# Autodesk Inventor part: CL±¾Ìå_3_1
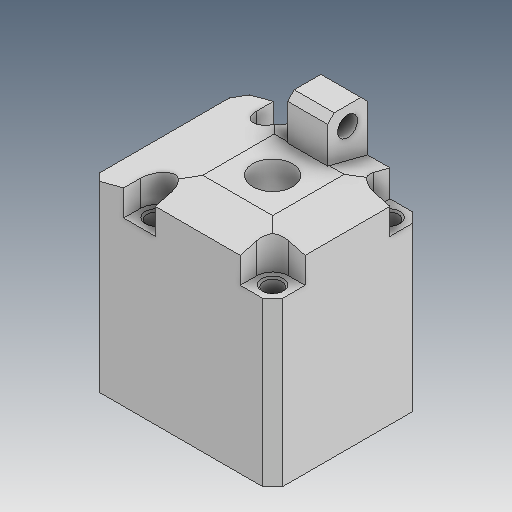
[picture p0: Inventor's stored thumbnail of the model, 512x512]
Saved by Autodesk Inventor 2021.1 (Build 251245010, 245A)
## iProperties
Created: 2019-04
Part Number: CL±¾Ìå_3_1
Material: Ogólny
Document SubType Name: Modeling
Designer: user
Density: 1 g/cm^3
Appearance: Domyślna
Author: user
Revision Number: ÈÎºÎ
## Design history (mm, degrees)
feature "ÊäÈë1"
feature "ÊäÈë2"
node "Bryła1"
node "Bryła2"
